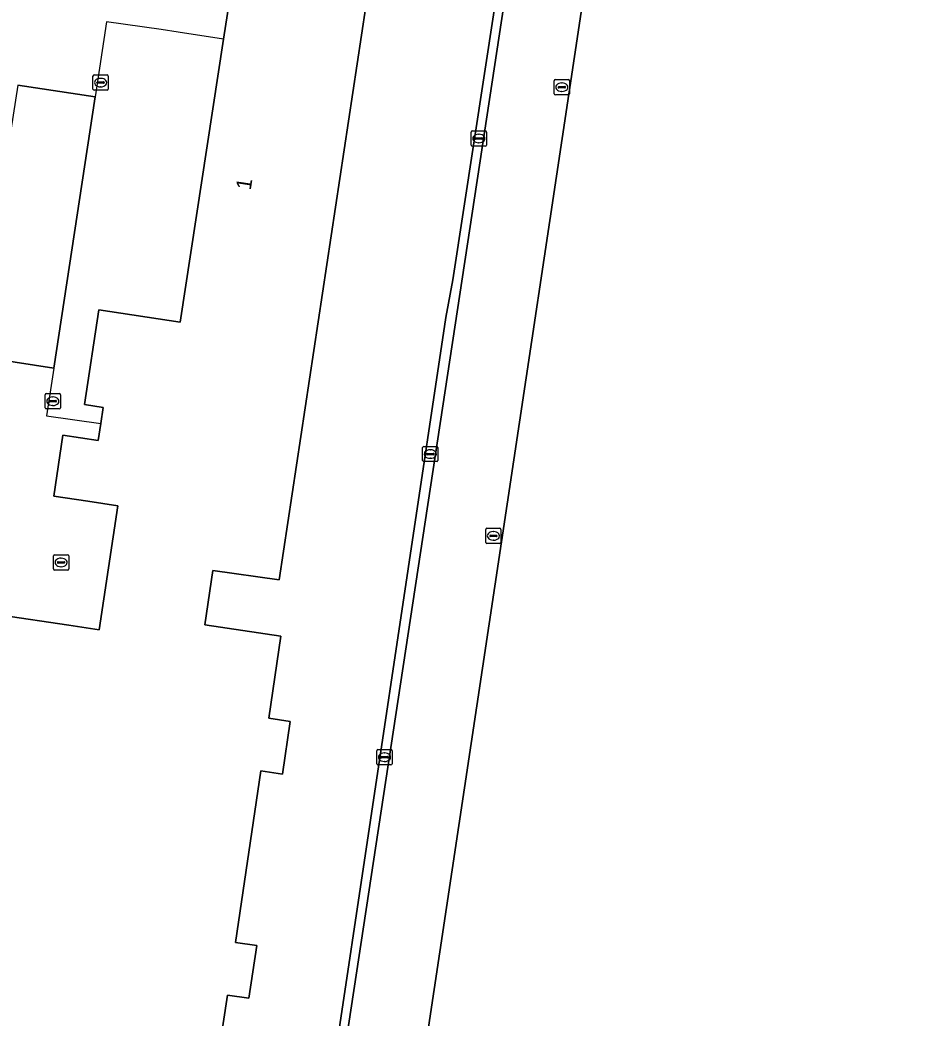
# Model space of a CAD drawing. Extents: x 161090 to 161692, y 379509 to 380907.
# Drawn here: x 161342.3 to 161400.7, y 380253.5 to 380319.1 of the extents above; entities that cross this region are included whole.
import ezdxf

# ---------------------------------------------------------------- set-up
doc = ezdxf.new("R2010")
doc.units = 0
for name, color, linetype in [('IMGEO_Erf', 7, 'Continuous'), ('IMGEO_Hek', 7, 'Continuous'), ('IMGEO_Kolk', 7, 'Continuous'), ('IMGEO_Pand', 7, 'Continuous'), ('IMGEO_Pand_nummerreeks', 7, 'Continuous'), ('IMGEO_Pand_overbouw', 7, 'Continuous'), ('IMGEO_Terreindeel_open', 7, 'Continuous'), ('IMGEO_Voetpad_open', 7, 'Continuous'), ('IMGEO_Waterleidingput', 7, 'Continuous')]:
    doc.layers.add(name, color=color, linetype=linetype)

msp = doc.modelspace()

# ---------------------------------------------------------------- linework, layer by layer
at = {"layer": 'IMGEO_Erf'}
for points in [[(161441.981, 380250), (161443.348, 380259.239), (161452.235, 380318.578), (161456.714, 380348.489), (161379.666, 380360.168), (161370.769, 380302.037), (161370.307, 380299.553), (161362.86, 380250), (161361.584, 380241.511), (161396.413, 380236.189), (161404.532, 380234.95), (161438.956, 380229.56)], [(161366.609, 380241.3), (161362.232, 380241.926), (161362.493, 380243.855), (161362.621, 380244.695), (161363.43, 380250), (161379.665, 380356.51), (161380.127, 380359.542), (161381.017, 380359.406), (161456.089, 380348.027), (161441.451, 380250), (161438.493, 380230.189)]]:
    msp.add_lwpolyline(points, close=True, dxfattribs=at)
at = {"layer": 'IMGEO_Hek'}
for points in [[(161379.666, 380360.168), (161370.769, 380302.037)], [(161370.769, 380302.037), (161370.307, 380299.553)], [(161370.307, 380299.553), (161362.86, 380250), (161361.584, 380241.511)]]:
    msp.add_lwpolyline(points, dxfattribs=at)
at = {"layer": 'IMGEO_Kolk'}
for p, q in [((161347.105, 380314.576), (161347.105, 380315.428)), ((161347.18, 380315.502), (161348.032, 380315.502)), ((161347.593, 380315.282), (161347.618, 380315.282)), ((161348.106, 380315.428), (161348.106, 380314.576)), ((161348.032, 380314.502), (161347.18, 380314.502)), ((161347.364, 380314.996), (161347.364, 380315.008)), ((161347.802, 380314.959), (161347.404, 380314.959)), ((161347.407, 380315.045), (161347.805, 380315.045)), ((161347.616, 380314.722), (161347.591, 380314.722)), ((161347.848, 380315.008), (161347.848, 380314.996)), ((161372.043, 380311.826), (161372.895, 380311.826)), ((161371.968, 380310.9), (161371.968, 380311.752)), ((161372.227, 380311.32), (161372.227, 380311.332)), ((161372.665, 380311.283), (161372.267, 380311.283)), ((161372.27, 380311.369), (161372.668, 380311.369)), ((161372.456, 380311.606), (161372.481, 380311.606)), ((161372.711, 380311.332), (161372.711, 380311.32)), ((161372.969, 380311.752), (161372.969, 380310.9)), ((161372.895, 380310.826), (161372.043, 380310.826)), ((161372.479, 380311.046), (161372.454, 380311.046)), ((161343.963, 380293.635), (161343.963, 380294.487)), ((161344.038, 380294.561), (161344.89, 380294.561)), ((161344.222, 380294.055), (161344.222, 380294.067)), ((161344.265, 380294.104), (161344.663, 380294.104)), ((161344.451, 380294.341), (161344.476, 380294.341)), ((161344.706, 380294.067), (161344.706, 380294.055)), ((161344.964, 380294.487), (161344.964, 380293.635)), ((161344.89, 380293.561), (161344.038, 380293.561)), ((161344.66, 380294.018), (161344.262, 380294.018)), ((161344.474, 380293.781), (161344.449, 380293.781)), ((161368.775, 380290.163), (161368.775, 380291.015)), ((161368.85, 380291.089), (161369.702, 380291.089)), ((161369.263, 380290.869), (161369.288, 380290.869)), ((161369.776, 380291.015), (161369.776, 380290.163)), ((161369.034, 380290.583), (161369.034, 380290.595)), ((161369.472, 380290.546), (161369.074, 380290.546)), ((161369.077, 380290.632), (161369.475, 380290.632)), ((161369.286, 380290.309), (161369.261, 380290.309)), ((161369.518, 380290.595), (161369.518, 380290.583)), ((161369.702, 380290.089), (161368.85, 380290.089)), ((161344.508, 380283.04), (161344.508, 380283.892)), ((161344.583, 380283.966), (161345.435, 380283.966)), ((161344.996, 380283.746), (161345.021, 380283.746)), ((161345.509, 380283.892), (161345.509, 380283.04)), ((161345.435, 380282.966), (161344.583, 380282.966)), ((161344.767, 380283.46), (161344.767, 380283.472)), ((161345.205, 380283.423), (161344.807, 380283.423)), ((161344.81, 380283.509), (161345.208, 380283.509)), ((161345.019, 380283.186), (161344.994, 380283.186)), ((161345.251, 380283.472), (161345.251, 380283.46)), ((161365.839, 380271.164), (161366.691, 380271.164)), ((161365.764, 380270.238), (161365.764, 380271.09)), ((161366.023, 380270.658), (161366.023, 380270.67)), ((161366.461, 380270.621), (161366.063, 380270.621)), ((161366.066, 380270.707), (161366.464, 380270.707)), ((161366.252, 380270.944), (161366.277, 380270.944)), ((161366.507, 380270.67), (161366.507, 380270.658)), ((161366.765, 380271.09), (161366.765, 380270.238)), ((161366.691, 380270.164), (161365.839, 380270.164)), ((161366.275, 380270.384), (161366.25, 380270.384))]:
    msp.add_line(p, q, dxfattribs=at)
for points in [[(161347.105, 380314.576), (161347.105, 380315.428)], [(161347.18, 380315.502), (161348.032, 380315.502)], [(161348.106, 380315.428), (161348.106, 380314.576)], [(161348.032, 380314.502), (161347.18, 380314.502)], [(161372.043, 380311.826), (161372.895, 380311.826)], [(161371.968, 380310.9), (161371.968, 380311.752)], [(161372.969, 380311.752), (161372.969, 380310.9)], [(161372.895, 380310.826), (161372.043, 380310.826)], [(161343.963, 380293.635), (161343.963, 380294.487)], [(161344.038, 380294.561), (161344.89, 380294.561)], [(161344.964, 380294.487), (161344.964, 380293.635)], [(161344.89, 380293.561), (161344.038, 380293.561)], [(161368.775, 380290.163), (161368.775, 380291.015)], [(161368.85, 380291.089), (161369.702, 380291.089)], [(161369.776, 380291.015), (161369.776, 380290.163)], [(161369.702, 380290.089), (161368.85, 380290.089)], [(161344.508, 380283.04), (161344.508, 380283.892)], [(161344.583, 380283.966), (161345.435, 380283.966)], [(161345.509, 380283.892), (161345.509, 380283.04)], [(161345.435, 380282.966), (161344.583, 380282.966)], [(161365.839, 380271.164), (161366.691, 380271.164)], [(161365.764, 380270.238), (161365.764, 380271.09)], [(161366.765, 380271.09), (161366.765, 380270.238)], [(161366.691, 380270.164), (161365.839, 380270.164)]]:
    msp.add_lwpolyline(points, dxfattribs=at)
for centre, radius, start, end in [((161347.182, 380315.426), 0.0765, 91.55205, 178.44795), ((161347.182, 380315.426), 0.0765, 91.55205, 178.44795), ((161348.03, 380315.426), 0.0765, 1.55205, 88.44795), ((161348.03, 380315.426), 0.0765, 1.55205, 88.44795), ((161347.182, 380314.578), 0.0765, 181.55205, 268.44795), ((161347.182, 380314.578), 0.0765, 181.55205, 268.44795), ((161347.404, 380315.005), 0.0403, 85.87752, 175.75265), ((161347.401, 380314.995), 0.0366, 178.93798, 274.71019), ((161347.805, 380315.002), 0.043, 264.86636, 352.45326), ((161347.809, 380315.007), 0.0386, 1.73085, 96.63898), ((161348.03, 380314.578), 0.0765, 271.55205, 358.44795), ((161348.03, 380314.578), 0.0765, 271.55205, 358.44795), ((161372.045, 380311.75), 0.0765, 91.55205, 178.44795), ((161372.045, 380311.75), 0.0765, 91.55205, 178.44795), ((161372.893, 380311.75), 0.0765, 1.55205, 88.44795), ((161372.893, 380311.75), 0.0765, 1.55205, 88.44795), ((161372.267, 380311.329), 0.0403, 85.87752, 175.75265), ((161372.264, 380311.319), 0.0366, 178.93798, 274.71019), ((161372.668, 380311.326), 0.043, 264.86636, 352.45326), ((161372.672, 380311.331), 0.0386, 1.73085, 96.63898), ((161372.045, 380310.902), 0.0765, 181.55205, 268.44795), ((161372.045, 380310.902), 0.0765, 181.55205, 268.44795), ((161372.893, 380310.902), 0.0765, 271.55205, 358.44795), ((161372.893, 380310.902), 0.0765, 271.55205, 358.44795), ((161344.04, 380294.485), 0.0765, 91.55205, 178.44795), ((161344.04, 380294.485), 0.0765, 91.55205, 178.44795), ((161344.262, 380294.064), 0.0403, 85.87752, 175.75265), ((161344.667, 380294.066), 0.0386, 1.73085, 96.63898), ((161344.888, 380294.485), 0.0765, 1.55205, 88.44795), ((161344.888, 380294.485), 0.0765, 1.55205, 88.44795), ((161344.04, 380293.637), 0.0765, 181.55205, 268.44795), ((161344.04, 380293.637), 0.0765, 181.55205, 268.44795), ((161344.259, 380294.054), 0.0366, 178.93798, 274.71019), ((161344.663, 380294.061), 0.043, 264.86636, 352.45326), ((161344.888, 380293.637), 0.0765, 271.55205, 358.44795), ((161344.888, 380293.637), 0.0765, 271.55205, 358.44795), ((161368.852, 380291.013), 0.0765, 91.55205, 178.44795), ((161368.852, 380291.013), 0.0765, 91.55205, 178.44795), ((161369.7, 380291.013), 0.0765, 1.55205, 88.44795), ((161369.7, 380291.013), 0.0765, 1.55205, 88.44795), ((161368.852, 380290.165), 0.0765, 181.55205, 268.44795), ((161368.852, 380290.165), 0.0765, 181.55205, 268.44795), ((161369.074, 380290.592), 0.0403, 85.87752, 175.75265), ((161369.071, 380290.582), 0.0366, 178.93798, 274.71019), ((161369.475, 380290.589), 0.043, 264.86636, 352.45326), ((161369.479, 380290.594), 0.0386, 1.73085, 96.63898), ((161369.7, 380290.165), 0.0765, 271.55205, 358.44795), ((161369.7, 380290.165), 0.0765, 271.55205, 358.44795), ((161344.585, 380283.89), 0.0765, 91.55205, 178.44795), ((161344.585, 380283.89), 0.0765, 91.55205, 178.44795), ((161345.433, 380283.89), 0.0765, 1.55205, 88.44795), ((161345.433, 380283.89), 0.0765, 1.55205, 88.44795), ((161344.585, 380283.042), 0.0765, 181.55205, 268.44795), ((161344.585, 380283.042), 0.0765, 181.55205, 268.44795), ((161344.807, 380283.469), 0.0403, 85.87752, 175.75265), ((161344.804, 380283.459), 0.0366, 178.93798, 274.71019), ((161345.208, 380283.466), 0.043, 264.86636, 352.45326), ((161345.212, 380283.471), 0.0386, 1.73085, 96.63898), ((161345.433, 380283.042), 0.0765, 271.55205, 358.44795), ((161345.433, 380283.042), 0.0765, 271.55205, 358.44795), ((161365.841, 380271.088), 0.0765, 91.55205, 178.44795), ((161365.841, 380271.088), 0.0765, 91.55205, 178.44795), ((161366.689, 380271.088), 0.0765, 1.55205, 88.44795), ((161366.689, 380271.088), 0.0765, 1.55205, 88.44795), ((161366.063, 380270.667), 0.0403, 85.87752, 175.75265), ((161366.06, 380270.657), 0.0366, 178.93798, 274.71019), ((161366.464, 380270.664), 0.043, 264.86636, 352.45326), ((161366.468, 380270.669), 0.0386, 1.73085, 96.63898), ((161365.841, 380270.24), 0.0765, 181.55205, 268.44795), ((161365.841, 380270.24), 0.0765, 181.55205, 268.44795), ((161366.689, 380270.24), 0.0765, 271.55205, 358.44795), ((161366.689, 380270.24), 0.0765, 271.55205, 358.44795)]:
    msp.add_arc(centre, radius, start, end, dxfattribs=at)
for centre, major_axis, ratio, start_param, end_param in [((161347.592, 380315.002), (-0.387, 0.002), 0.722429, 4.712389, 7.853982), ((161347.617, 380315.002), (-0.39, 0.002), 0.717154, 1.570796, 4.712389), ((161372.455, 380311.326), (-0.387, 0.002), 0.722429, 4.712389, 7.853982), ((161372.48, 380311.326), (-0.39, 0.002), 0.717154, 1.570796, 4.712389), ((161344.45, 380294.061), (-0.387, 0.002), 0.722429, 4.712389, 7.853982), ((161344.475, 380294.061), (-0.39, 0.002), 0.717154, 1.570796, 4.712389), ((161369.262, 380290.589), (-0.387, 0.002), 0.722429, 4.712389, 7.853982), ((161369.287, 380290.589), (-0.39, 0.002), 0.717154, 1.570796, 4.712389), ((161344.995, 380283.466), (-0.387, 0.002), 0.722429, 4.712389, 7.853982), ((161345.02, 380283.466), (-0.39, 0.002), 0.717154, 1.570796, 4.712389), ((161366.251, 380270.664), (-0.387, 0.002), 0.722429, 4.712389, 7.853982), ((161366.276, 380270.664), (-0.39, 0.002), 0.717154, 1.570796, 4.712389)]:
    msp.add_ellipse(centre, major_axis=major_axis, ratio=ratio, start_param=start_param, end_param=end_param, dxfattribs=at)
at = {"layer": 'IMGEO_Pand'}
for points in [[(161356.465, 380322.943), (161355.684, 380317.859), (161352.828, 380299.261), (161347.498, 380300.059), (161346.549, 380293.841), (161347.776, 380293.654), (161347.619, 380292.588), (161347.454, 380291.469), (161345.133, 380291.822), (161344.529, 380287.821), (161346.771, 380287.484), (161348.74, 380287.188), (161347.51, 380279.046), (161345.507, 380279.345), (161341.066, 380280.007)], [(161355.189, 380250), (161355.945, 380255.037), (161357.354, 380254.827), (161357.868, 380258.285), (161356.483, 380258.492), (161358.142, 380269.766), (161359.554, 380269.552), (161360.076, 380273.013), (161358.672, 380273.226), (161359.454, 380278.62), (161354.457, 380279.373), (161354.975, 380282.94), (161359.341, 380282.327), (161365.327, 380321.904)]]:
    msp.add_lwpolyline(points, dxfattribs=at)
msp.add_lwpolyline([(161347.246, 380314.062), (161342.154, 380314.837), (161341.703, 380311.871), (161340.744, 380312.017), (161340.646, 380311.385), (161338.893, 380300.18), (161339.881, 380300.03), (161339.843, 380299.782), (161339.423, 380297.015), (161344.534, 380296.237)], close=True, dxfattribs=at)
at = {"layer": 'IMGEO_Pand_overbouw'}
msp.add_lwpolyline([(161355.684, 380317.859), (161352.709, 380318.314), (161351.585, 380318.483), (161347.998, 380319.005), (161347.246, 380314.062), (161344.534, 380296.237), (161344.057, 380293.103), (161347.619, 380292.588), (161347.776, 380293.654), (161346.549, 380293.841), (161347.498, 380300.059), (161352.828, 380299.261)], close=True, dxfattribs=at)
at = {"layer": 'IMGEO_Terreindeel_open'}
for points in [[(161379.665, 380356.51), (161363.43, 380250), (161362.621, 380244.695), (161437.723, 380233.337), (161454.471, 380345.13)], [(161449.975, 380341.416), (161436.285, 380250), (161434.571, 380238.556), (161368.518, 380248.665), (161368.719, 380250), (161384, 380351.548)], [(161449.975, 380341.416), (161384, 380351.548), (161368.719, 380250), (161368.518, 380248.665), (161434.571, 380238.556), (161436.285, 380250)]]:
    msp.add_lwpolyline(points, close=True, dxfattribs=at)
at = {"layer": 'IMGEO_Voetpad_open'}
for points in [[(161362.86, 380250), (161370.307, 380299.553), (161370.769, 380302.037), (161379.666, 380360.168)], [(161341.066, 380280.007), (161345.507, 380279.345), (161347.51, 380279.046), (161348.74, 380287.188), (161346.771, 380287.484), (161344.529, 380287.821), (161345.133, 380291.822), (161347.454, 380291.469), (161347.619, 380292.588), (161347.776, 380293.654), (161346.549, 380293.841), (161347.498, 380300.059), (161352.828, 380299.261), (161355.684, 380317.859), (161356.465, 380322.943)], [(161365.327, 380321.904), (161359.341, 380282.327), (161354.975, 380282.94), (161354.457, 380279.373), (161359.454, 380278.62), (161358.672, 380273.226), (161360.076, 380273.013), (161359.554, 380269.552), (161358.142, 380269.766), (161356.483, 380258.492), (161357.868, 380258.285), (161357.354, 380254.827), (161355.945, 380255.037), (161355.189, 380250)], [(161342.154, 380314.837), (161347.246, 380314.062), (161344.534, 380296.237), (161339.423, 380297.015)]]:
    msp.add_lwpolyline(points, dxfattribs=at)
at = {"layer": 'IMGEO_Waterleidingput'}
for p, q in [((161377.422, 380314.274), (161377.422, 380315.126)), ((161377.497, 380315.2), (161378.349, 380315.2)), ((161378.423, 380315.126), (161378.423, 380314.274)), ((161377.681, 380314.694), (161377.681, 380314.706)), ((161378.119, 380314.657), (161377.721, 380314.657)), ((161377.724, 380314.743), (161378.122, 380314.743)), ((161377.933, 380314.42), (161377.908, 380314.42)), ((161377.91, 380314.98), (161377.935, 380314.98)), ((161378.165, 380314.706), (161378.165, 380314.694)), ((161378.349, 380314.2), (161377.497, 380314.2)), ((161372.923, 380284.784), (161372.923, 380285.636)), ((161372.998, 380285.71), (161373.85, 380285.71)), ((161373.924, 380285.636), (161373.924, 380284.784)), ((161373.182, 380285.204), (161373.182, 380285.216)), ((161373.62, 380285.167), (161373.222, 380285.167)), ((161373.225, 380285.253), (161373.623, 380285.253)), ((161373.434, 380284.93), (161373.409, 380284.93)), ((161373.411, 380285.49), (161373.436, 380285.49)), ((161373.666, 380285.216), (161373.666, 380285.204)), ((161373.85, 380284.71), (161372.998, 380284.71))]:
    msp.add_line(p, q, dxfattribs=at)
for points in [[(161377.422, 380314.274), (161377.422, 380315.126)], [(161377.497, 380315.2), (161378.349, 380315.2)], [(161378.423, 380315.126), (161378.423, 380314.274)], [(161378.349, 380314.2), (161377.497, 380314.2)], [(161372.923, 380284.784), (161372.923, 380285.636)], [(161372.998, 380285.71), (161373.85, 380285.71)], [(161373.924, 380285.636), (161373.924, 380284.784)], [(161373.85, 380284.71), (161372.998, 380284.71)]]:
    msp.add_lwpolyline(points, dxfattribs=at)
for centre, radius, start, end in [((161377.499, 380315.124), 0.0765, 91.55205, 178.44795), ((161377.499, 380315.124), 0.0765, 91.55205, 178.44795), ((161378.347, 380315.124), 0.0765, 1.55205, 88.44795), ((161378.347, 380315.124), 0.0765, 1.55205, 88.44795), ((161377.721, 380314.703), 0.0403, 85.87752, 175.75265), ((161377.718, 380314.693), 0.0366, 178.93798, 274.71019), ((161378.122, 380314.7), 0.043, 264.86636, 352.45326), ((161378.126, 380314.705), 0.0386, 1.73085, 96.63898), ((161377.499, 380314.276), 0.0765, 181.55205, 268.44795), ((161377.499, 380314.276), 0.0765, 181.55205, 268.44795), ((161378.347, 380314.276), 0.0765, 271.55205, 358.44795), ((161378.347, 380314.276), 0.0765, 271.55205, 358.44795), ((161373, 380285.634), 0.0765, 91.55205, 178.44795), ((161373, 380285.634), 0.0765, 91.55205, 178.44795), ((161373.848, 380285.634), 0.0765, 1.55205, 88.44795), ((161373.848, 380285.634), 0.0765, 1.55205, 88.44795), ((161373.222, 380285.213), 0.0403, 85.87752, 175.75265), ((161373.219, 380285.203), 0.0366, 178.93798, 274.71019), ((161373.623, 380285.21), 0.043, 264.86636, 352.45326), ((161373.627, 380285.215), 0.0386, 1.73085, 96.63898), ((161373, 380284.786), 0.0765, 181.55205, 268.44795), ((161373, 380284.786), 0.0765, 181.55205, 268.44795), ((161373.848, 380284.786), 0.0765, 271.55205, 358.44795), ((161373.848, 380284.786), 0.0765, 271.55205, 358.44795)]:
    msp.add_arc(centre, radius, start, end, dxfattribs=at)
for centre, major_axis, ratio, start_param, end_param in [((161377.909, 380314.7), (-0.387, 0.002), 0.722429, 4.712389, 7.853982), ((161377.934, 380314.7), (-0.39, 0.002), 0.717154, 1.570796, 4.712389), ((161373.41, 380285.21), (-0.387, 0.002), 0.722429, 4.712389, 7.853982), ((161373.435, 380285.21), (-0.39, 0.002), 0.717154, 1.570796, 4.712389)]:
    msp.add_ellipse(centre, major_axis=major_axis, ratio=ratio, start_param=start_param, end_param=end_param, dxfattribs=at)

# ---------------------------------------------------------------- texts
at = {"layer": 'IMGEO_Pand_nummerreeks'}
msp.add_text('1', height=1, rotation=81.26833, dxfattribs=at).set_placement((161357.474, 380307.903))

doc.saveas('drawing.dxf')
